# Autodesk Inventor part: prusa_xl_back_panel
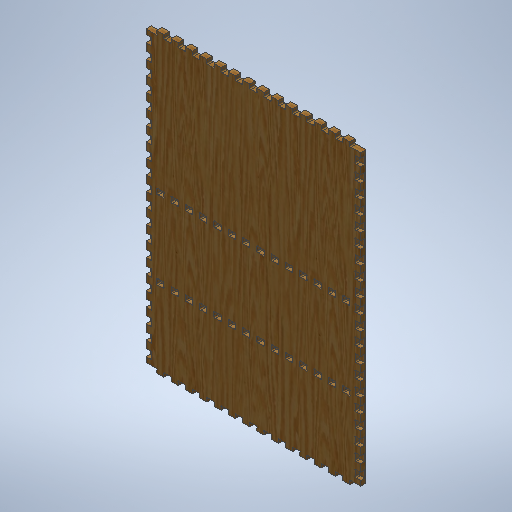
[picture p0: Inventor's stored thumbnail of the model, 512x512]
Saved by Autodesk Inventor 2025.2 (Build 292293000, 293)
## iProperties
Created: 2025-03
Part Number: prusa_xl_back_panel
Material: Plywood, Finish
Document SubType Name: Modeling
Designer: BennF
Density: 0.552 g/cm^3
Appearance: Plywood - New
Author: BennF
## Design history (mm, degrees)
sketch "Sketch2"
  geometry: L1 (360, 484.5)-(-360, 484.5); L2 (-360, 484.5)-(-360, -484.5); L3 (-360, -484.5)-(360, -484.5); L4 (360, -484.5)-(360, 484.5); 3 further points
  constraints: 8 end point, 2 midpoint, 2 parallel, 1 horizontal, 1 horizontal alignment, 1 perpendicular, 1 vertical alignment
  dimensions: "d0" = 720 distance of L1.start L1.end (= prusa_xl_width); "d1" = 969 distance of L3.end L1.start (= prusa_xl_height - 2 x finger_depth)
extrude "base_material" new body sketch "Sketch2" distance "d2" = 18 (= thickness); taper "d3" = 0 deg
sketch "Sketch3"
  geometry: L1 (-323.9, 484.5)-(-323.9, 498); L2 (-323.9, 498)-(-300.1, 498); L3 (-300.1, 498)-(-300.1, 484.5); L4 (-360, -484.5)-(-360, 484.5) reference; L5 (-323.9, -484.5)-(-323.9, -498); L6 (-323.9, -498)-(-300.1, -498); L7 (-300.1, -498)-(-300.1, -484.5); L8 (-275.9, 484.5)-(-275.9, 498); L9 (-275.9, 498)-(-252.1, 498); L10 (-252.1, 498)-(-252.1, 484.5); L11 (-275.9, -484.5)-(-275.9, -498); L12 (-275.9, -498)-(-252.1, -498); L13 (-252.1, -498)-(-252.1, -484.5); L14 (-227.9, 484.5)-(-227.9, 498); L15 (-227.9, 498)-(-204.1, 498); L16 (-204.1, 498)-(-204.1, 484.5); L17 (-227.9, -484.5)-(-227.9, -498); L18 (-227.9, -498)-(-204.1, -498); L19 (-204.1, -498)-(-204.1, -484.5); L20 (-179.9, 484.5)-(-179.9, 498); L21 (-179.9, 498)-(-156.1, 498); L22 (-156.1, 498)-(-156.1, 484.5); L23 (-179.9, -484.5)-(-179.9, -498); L24 (-179.9, -498)-(-156.1, -498); L25 (-156.1, -498)-(-156.1, -484.5); L26 (-131.9, 484.5)-(-131.9, 498); L27 (-131.9, 498)-(-108.1, 498); L28 (-108.1, 498)-(-108.1, 484.5); L29 (-131.9, -484.5)-(-131.9, -498); L30 (-131.9, -498)-(-108.1, -498); L31 (-108.1, -498)-(-108.1, -484.5); L32 (-83.9, 484.5)-(-83.9, 498); L33 (-83.9, 498)-(-60.1, 498); L34 (-60.1, 498)-(-60.1, 484.5); L35 (-83.9, -484.5)-(-83.9, -498); L36 (-83.9, -498)-(-60.1, -498); L37 (-60.1, -498)-(-60.1, -484.5); L38 (-35.9, 484.5)-(-35.9, 498); L39 (-35.9, 498)-(-12.1, 498); L40 (-12.1, 498)-(-12.1, 484.5); L41 (-35.9, -484.5)-(-35.9, -498); L42 (-35.9, -498)-(-12.1, -498); L43 (-12.1, -498)-(-12.1, -484.5); L44 (12.1, 484.5)-(12.1, 498); L45 (12.1, 498)-(35.9, 498); L46 (35.9, 498)-(35.9, 484.5); L47 (12.1, -484.5)-(12.1, -498); L48 (12.1, -498)-(35.9, -498); L49 (35.9, -498)-(35.9, -484.5); L50 (60.1, 484.5)-(60.1, 498); L51 (60.1, 498)-(83.9, 498); L52 (83.9, 498)-(83.9, 484.5); L53 (60.1, -484.5)-(60.1, -498); L54 (60.1, -498)-(83.9, -498); L55 (83.9, -498)-(83.9, -484.5); L56 (108.1, 484.5)-(108.1, 498); L57 (108.1, 498)-(131.9, 498); L58 (131.9, 498)-(131.9, 484.5); L59 (108.1, -484.5)-(108.1, -498); L60 (108.1, -498)-(131.9, -498); L61 (131.9, -498)-(131.9, -484.5); L62 (156.1, 484.5)-(156.1, 498); L63 (156.1, 498)-(179.9, 498); L64 (179.9, 498)-(179.9, 484.5)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; 55 further points
  constraints: 168 end point, 104 horizontal alignment, 52 parallel, 26 collinear, 4 perpendicular, 2 equal length, 2 vertical, 1 vertical alignment, 6 other
  dimensions: "d4" = 23.8 distance of L1.end L2.end (= finger_width - connection_clearence); "d5" = 13.5 distance of L1.start L1.end (= finger_depth - hidden_depth); "d6" = 36.1 distance between parallel lines of L1 L4 (= prusa_xl_width_finger_distance + 0.5 x connection_clearence); "d9" = 48 distance of L1.start L8.start (= finger_distance)
extrude "joints_1" join sketch "Sketch3" distance "d14" = 18 (= thickness); taper "d15" = 0 deg
sketch "Sketch5"
  geometry: L1 (-360, 468)-(-341.8, 468); L2 (-341.8, 468)-(-341.8, 444); L3 (-341.8, 444)-(-360, 444); L4 (-300.1, 498)-(-323.9, 498) reference; L5 (360, 468)-(341.8, 468); L6 (341.8, 468)-(341.8, 444); L7 (341.8, 444)-(360, 444); L8 (-360, 420)-(-341.8, 420); L9 (-341.8, 420)-(-341.8, 396); L10 (-341.8, 396)-(-360, 396); L11 (360, 420)-(341.8, 420); L12 (341.8, 420)-(341.8, 396); L13 (341.8, 396)-(360, 396); L14 (-360, 372)-(-341.8, 372); L15 (-341.8, 372)-(-341.8, 348); L16 (-341.8, 348)-(-360, 348); L17 (360, 372)-(341.8, 372); L18 (341.8, 372)-(341.8, 348); L19 (341.8, 348)-(360, 348); L20 (-360, 324)-(-341.8, 324); L21 (-341.8, 324)-(-341.8, 300); L22 (-341.8, 300)-(-360, 300); L23 (360, 324)-(341.8, 324); L24 (341.8, 324)-(341.8, 300); L25 (341.8, 300)-(360, 300); L26 (-360, 276)-(-341.8, 276); L27 (-341.8, 276)-(-341.8, 252); L28 (-341.8, 252)-(-360, 252); L29 (360, 276)-(341.8, 276); L30 (341.8, 276)-(341.8, 252); L31 (341.8, 252)-(360, 252); L32 (-360, 228)-(-341.8, 228); L33 (-341.8, 228)-(-341.8, 204); L34 (-341.8, 204)-(-360, 204); L35 (360, 228)-(341.8, 228); L36 (341.8, 228)-(341.8, 204); L37 (341.8, 204)-(360, 204); L38 (-360, 180)-(-341.8, 180); L39 (-341.8, 180)-(-341.8, 156); L40 (-341.8, 156)-(-360, 156); L41 (360, 180)-(341.8, 180); L42 (341.8, 180)-(341.8, 156); L43 (341.8, 156)-(360, 156); L44 (-360, 132)-(-341.8, 132); L45 (-341.8, 132)-(-341.8, 108); L46 (-341.8, 108)-(-360, 108); L47 (360, 132)-(341.8, 132); L48 (341.8, 132)-(341.8, 108); L49 (341.8, 108)-(360, 108); L50 (-360, 84)-(-341.8, 84); L51 (-341.8, 84)-(-341.8, 60); L52 (-341.8, 60)-(-360, 60); L53 (360, 84)-(341.8, 84); L54 (341.8, 84)-(341.8, 60); L55 (341.8, 60)-(360, 60); L56 (-360, 36)-(-341.8, 36); L57 (-341.8, 36)-(-341.8, 12); L58 (-341.8, 12)-(-360, 12); L59 (360, 36)-(341.8, 36); L60 (341.8, 36)-(341.8, 12); L61 (341.8, 12)-(360, 12); L62 (-360, -12)-(-341.8, -12); L63 (-341.8, -12)-(-341.8, -36); L64 (-341.8, -36)-(-360, -36)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; 84 further points
  constraints: 240 end point, 152 vertical alignment, 76 parallel, 38 collinear, 4 perpendicular, 3 equal length, 2 coincident, 2 horizontal, 1 horizontal alignment, 7 other
  dimensions: "d18" = 24 distance of L1.end L2.end (= finger_width); "d19" = 18.2 distance of L1.start L1.end (= thickness + connection_clearence); "d20" = 30 distance between parallel lines of L1 L4 (= prusa_xl_height_finger_distance - hidden_depth); "d23" = 48 distance of L1.start L8.start (= finger_distance)
extrude "joints_2" cut sketch "Sketch5" distance "d28" = 13.5 (= thickness - hidden_depth); taper "d29" = 0 deg
sketch "Sketch6"
  geometry: L1 (-324, 40.167)-(-300, 40.167); L2 (-300, 40.167)-(-300, 22.167); L3 (-300, 22.167)-(-324, 22.167); L4 (-324, 22.167)-(-324, 40.167); L5 (-324, -222.167)-(-300, -222.167); L6 (-300, -222.167)-(-300, -240.167); L7 (-300, -240.167)-(-324, -240.167); L8 (-324, -240.167)-(-324, -222.167); L9 (-360, 484.5)-(-323.9, 484.5) reference; L10 (-360, 36)-(-360, 60) reference; L11 (-276, 40.167)-(-252, 40.167); L12 (-276, 22.167)-(-276, 40.167); L13 (-252, 22.167)-(-276, 22.167); L14 (-252, 40.167)-(-252, 22.167); L15 (-252, -222.167)-(-252, -240.167); L16 (-276, -222.167)-(-252, -222.167); L17 (-276, -240.167)-(-276, -222.167); L18 (-252, -240.167)-(-276, -240.167); L19 (-228, 40.167)-(-204, 40.167); L20 (-228, 22.167)-(-228, 40.167); L21 (-204, 22.167)-(-228, 22.167); L22 (-204, 40.167)-(-204, 22.167); L23 (-204, -222.167)-(-204, -240.167); L24 (-228, -222.167)-(-204, -222.167); L25 (-228, -240.167)-(-228, -222.167); L26 (-204, -240.167)-(-228, -240.167); L27 (-180, 40.167)-(-156, 40.167); L28 (-180, 22.167)-(-180, 40.167); L29 (-156, 22.167)-(-180, 22.167); L30 (-156, 40.167)-(-156, 22.167); L31 (-156, -222.167)-(-156, -240.167); L32 (-180, -222.167)-(-156, -222.167); L33 (-180, -240.167)-(-180, -222.167); L34 (-156, -240.167)-(-180, -240.167); L35 (-132, 40.167)-(-108, 40.167); L36 (-132, 22.167)-(-132, 40.167); L37 (-108, 22.167)-(-132, 22.167); L38 (-108, 40.167)-(-108, 22.167); L39 (-108, -222.167)-(-108, -240.167); L40 (-132, -222.167)-(-108, -222.167); L41 (-132, -240.167)-(-132, -222.167); L42 (-108, -240.167)-(-132, -240.167); L43 (-84, 40.167)-(-60, 40.167); L44 (-84, 22.167)-(-84, 40.167); L45 (-60, 22.167)-(-84, 22.167); L46 (-60, 40.167)-(-60, 22.167); L47 (-60, -222.167)-(-60, -240.167); L48 (-84, -222.167)-(-60, -222.167); L49 (-84, -240.167)-(-84, -222.167); L50 (-60, -240.167)-(-84, -240.167); L51 (-36, 40.167)-(-12, 40.167); L52 (-36, 22.167)-(-36, 40.167); L53 (-12, 22.167)-(-36, 22.167); L54 (-12, 40.167)-(-12, 22.167); L55 (-12, -222.167)-(-12, -240.167); L56 (-36, -222.167)-(-12, -222.167); L57 (-36, -240.167)-(-36, -222.167); L58 (-12, -240.167)-(-36, -240.167); L59 (12, 40.167)-(36, 40.167); L60 (12, 22.167)-(12, 40.167); L61 (36, 22.167)-(12, 22.167); L62 (36, 40.167)-(36, 22.167); L63 (36, -222.167)-(36, -240.167); L64 (12, -222.167)-(36, -222.167)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
  constraints: 224 end point, 28 point on line, 4 parallel, 3 horizontal, 2 collinear, 2 perpendicular, 207 other
  dimensions: "d31" = 24 distance of L1.start L1.end (= finger_width); "d32" = 18 distance of L3.end L1.start (derived); "d33" = 444.33333 distance between parallel lines of L1 L9 (= box_height_1 + box_clearence_1); "d34" = 244.33333 distance between parallel lines of L5 L3 (= box_height_2 + box_clearence_1); "d35" = 36 distance between parallel lines of L4 L10 (= prusa_xl_width_finger_distance); "d38" = 48 distance of L1.start L11.start (= finger_distance)
extrude "joints_3" cut sketch "Sketch6" distance "d43" = 13.5 (= thickness - hidden_depth); taper "d44" = 0 deg
sketch "Sketch7" dims "d45" = 6 (= dogbone_diameter)
  geometry: L1 (-360, 484.5)-(-323.9, 484.5) reference; L2 (-300.1, 484.5)-(-275.9, 484.5) reference; L3 (-323.9, 484.5)-(-336, 496.6); L4 (-336, 496.6)-(-348.1, 484.5); L5 (-300.1, 484.5)-(-300.1, 498) reference; L6 (-300.1, 484.5)-(-288, 496.6); L7 (-288, 496.6)-(-275.9, 484.5); L8 (-323.9, -484.5)-(-360, -484.5) reference; L9 (-275.9, -484.5)-(-300.1, -484.5) reference; L10 (-323.9, -484.5)-(-323.9, -498) reference; L11 (-300.1, -484.5)-(-288, -496.6); L12 (-288, -496.6)-(-275.9, -484.5); L13 (-323.9, -484.5)-(-336, -496.6); L14 (-336, -496.6)-(-348.1, -484.5); 108 further points
  constraints: 53 horizontal, 16 end point, 10 perpendicular, 6 point on line, 272 other
  dimensions: "d48" = 48 distance of point (-326.021, 486.621) point (-278.021, 486.621) (= finger_distance)
extrude "dogbones_1" cut sketch "Sketch7" distance "d67" = 18 (= thickness); taper "d68" = 0 deg
sketch "Sketch8" dims "d71" = 6 (= dogbone_diameter)
  geometry: L1 (-360, 468)-(-341.8, 468) reference; L2 (-360, 444)-(-360, 468) reference; L3 (-341.8, 444)-(-360, 444) reference; L4 (-341.8, 468)-(-341.8, 444) reference; L5 (360, 444)-(341.8, 444) reference; L6 (360, 468)-(360, 444) reference; L7 (341.8, 468)-(360, 468) reference; L8 (341.8, 444)-(341.8, 468) reference; L9 (-300, 22.167)-(-324, 22.167) reference; L10 (-300, 40.167)-(-300, 22.167) reference; L11 (-324, 40.167)-(-300, 40.167) reference; L12 (-324, 22.167)-(-324, 40.167) reference; L13 (-300, -240.167)-(-324, -240.167) reference; L14 (-300, -222.167)-(-300, -240.167) reference; L15 (-324, -222.167)-(-300, -222.167) reference; L16 (-324, -240.167)-(-324, -222.167) reference; L17 (-341.8, 468)-(-353.8, 456); L18 (-353.8, 456)-(-341.8, 444); L19 (341.8, 468)-(360, 468) reference; L20 (341.8, 468)-(353.8, 456); L21 (353.8, 456)-(341.8, 444); L22 (-324, 22.167)-(-300, 40.167); L23 (-300, 22.167)-(-324, 40.167); L24 (-324, -240.167)-(-324, -222.167) reference; L25 (-324, -240.167)-(-300, -222.167); L26 (-324, -222.167)-(-300, -240.167); 372 further points
  constraints: 105 horizontal, 77 vertical, 16 end point, 12 point on line, 4 perpendicular, 1 parallel, 936 other
  dimensions: "d74" = 48 distance of point (-343.921, 465.879) point (-343.921, 417.879) (= finger_distance); "d81" = 48 distance of point (-321.6, 38.367) point (-273.6, 38.367) (= finger_distance)
extrude "dogbones_2" cut sketch "Sketch8" distance "d69" = 13.5 (= thickness - hidden_depth); taper "d70" = 0 deg
body "Solid1"
node "Sketch Rectangular Pattern1" dims "d9" = 48 (= finger_distance), "d12" = 10
node "Sketch Rectangular Pattern2" dims "d23" = 48 (= finger_distance), "d26" = 10
node "Sketch Rectangular Pattern3" dims "d38" = 48 (= finger_distance), "d41" = 10
node "Sketch Rectangular Pattern4" dims "d48" = 48 (= finger_distance), "d51" = 10
node "Projected Loop9"
node "Projected Loop10"
node "Projected Loop11"
node "Projected Loop12"
node "Sketch Rectangular Pattern7" dims "d74" = 48 (= finger_distance), "d77" = 10
node "Sketch Rectangular Pattern8" dims "d81" = 48 (= finger_distance), "d84" = 10
other parameters: "mill_bit" = 6 [user parameter], "thickness" = 18 [user parameter; used in 7 equation terms], "hidden_depth" = 4.5 [user parameter; used in 5 equation terms], "finger_depth" = 18 [user parameter; used in 2 equation terms], "finger_width" = 24 [user parameter; used in 3 equation terms], "finger_distance" = 48 [user parameter; used in 6 equation terms], "dogbone_angle" = 45 deg [user parameter], "dogbone_diameter" = 6 [user parameter; used in 2 equation terms], "prusa_xl_depth_finger_distance" = 36 [user parameter], "prusa_xl_height" = 1005 [user parameter; used in 1 equation term], "prusa_xl_height_finger_distance" = 34.5 [user parameter; used in 1 equation term], "prusa_xl_width" = 720 [user parameter; used in 1 equation term], "prusa_xl_width_finger_distance" = 36 [user parameter; used in 2 equation terms], "prusa_xl_shelf_depth" = 702 [user parameter], "prusa_xl_shelf_width" = 684 [user parameter], "box_height_1" = 435 [user parameter; used in 1 equation term], "box_height_2" = 235 [user parameter; used in 1 equation term], "box_clearence_1" = 9.33333 [user parameter; used in 2 equation terms], "connection_clearence" = 0.2 [user parameter; used in 3 equation terms], "sla_width" = 1296 [user parameter], "back_distance" = 5 [user parameter], "back_connection_depth" = 5 [user parameter], "storage_width_2" = 322 [user parameter], "box_clearence_2" = 24.33333 [user parameter], "shelf_depth_finger_distance" = 39 [user parameter], "connection_back_clearence" = 0 [user parameter], "thickness_back" = 6 [user parameter], "finger_depth_middle" = 8 [user parameter], "box_height_3" = 285 [user parameter], "bowden_tube_diameter" = 4 [user parameter], "connector_width_offset" = 105 [user parameter], "connector_width" = 26 [user parameter], "connector_depth" = 16 [user parameter]
